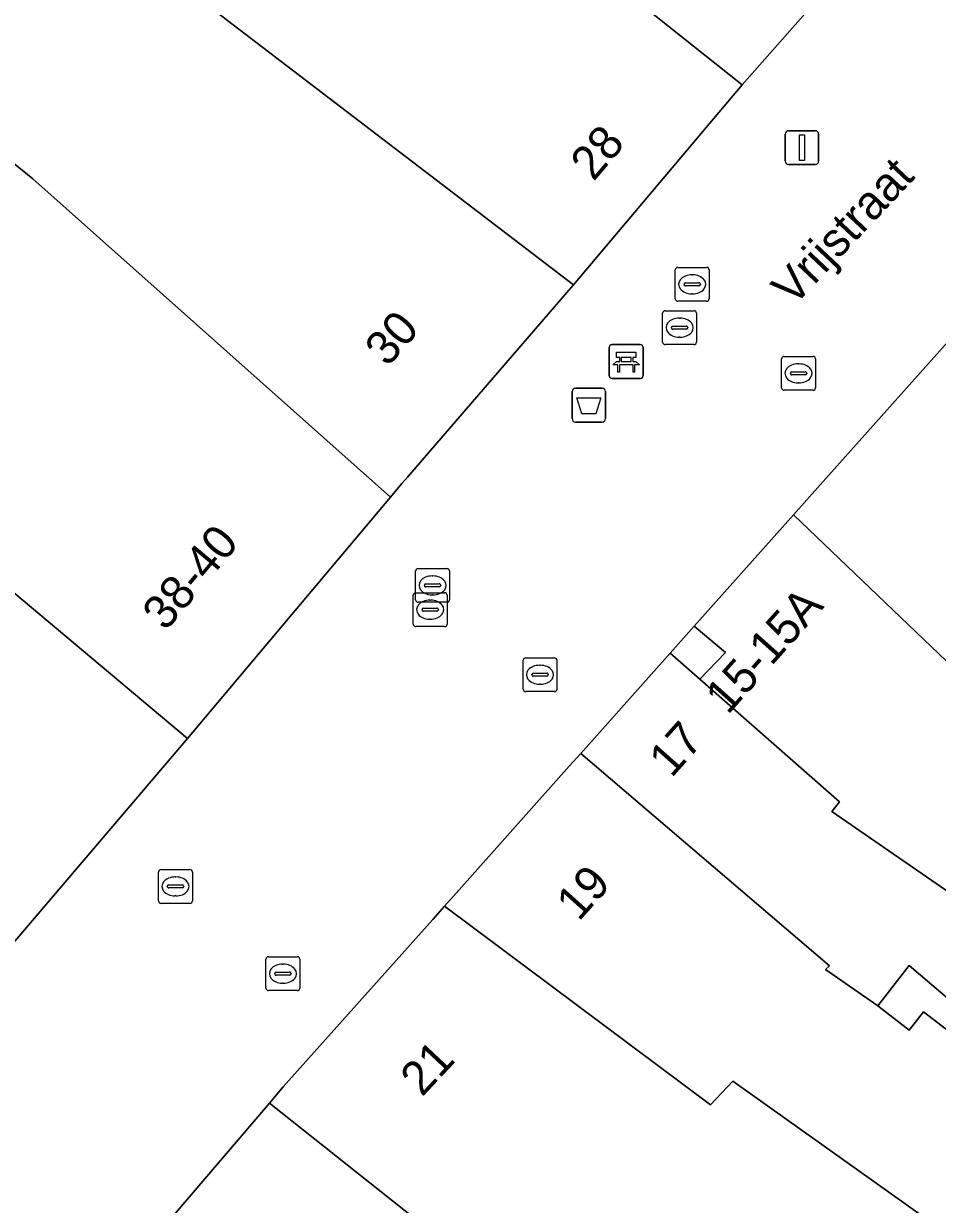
# Model space of a CAD drawing. Extents: x 161087 to 161926, y 382572 to 383873.
# Drawn here: x 161180.41 to 161207.42, y 383266.71 to 383301.6 of the extents above; entities that cross this region are included whole.
import ezdxf

# ---------------------------------------------------------------- set-up
doc = ezdxf.new("R2010")
doc.units = 0
for name, color, linetype in [('IMGEO_Afvalbak', 7, 'Continuous'), ('IMGEO_Bank', 7, 'Continuous'), ('IMGEO_Erf', 7, 'Continuous'), ('IMGEO_Kolk', 7, 'Continuous'), ('IMGEO_Lichtmast', 7, 'Continuous'), ('IMGEO_Openbare_ruimte_label', 7, 'Continuous'), ('IMGEO_Pand', 7, 'Continuous'), ('IMGEO_Pand_nummerreeks', 7, 'Continuous'), ('IMGEO_Pand_overbouw', 7, 'Continuous'), ('IMGEO_Rioolput', 7, 'Continuous'), ('IMGEO_Voetgangersgebied_open', 7, 'Continuous')]:
    doc.layers.add(name, color=color, linetype=linetype)

msp = doc.modelspace()

# ---------------------------------------------------------------- linework, layer by layer
at = {"layer": 'IMGEO_Afvalbak'}
for p, q in [((161196.62, 383289.925), (161196.62, 383290.725)), ((161196.62, 383290.725), (161196.62, 383289.925)), ((161196.72, 383290.825), (161197.51, 383290.825)), ((161197.51, 383290.825), (161196.72, 383290.825)), ((161197.61, 383290.725), (161197.61, 383289.925)), ((161197.61, 383289.925), (161197.61, 383290.725)), ((161197.51, 383289.825), (161196.72, 383289.825)), ((161196.72, 383289.825), (161197.51, 383289.825))]:
    msp.add_line(p, q, dxfattribs=at)
msp.add_lwpolyline([(161196.763, 383290.539), (161197.467, 383290.539), (161197.318, 383290.069), (161196.912, 383290.069), (161196.763, 383290.539)], dxfattribs=at)
for centre, start, end in [((161196.72, 383290.725), 90, 180), ((161196.72, 383290.725), 90, 180), ((161197.51, 383290.725), 0, 90), ((161197.51, 383290.725), 360, 90), ((161196.72, 383289.925), 180, 270), ((161196.72, 383289.925), 180, 270), ((161197.51, 383289.925), 270, 0), ((161197.51, 383289.925), 270, 0)]:
    msp.add_arc(centre, 0.1, start, end, dxfattribs=at)
at = {"layer": 'IMGEO_Bank'}
for p, q in [((161197.72, 383291.188), (161197.72, 383292.029)), ((161197.72, 383292.029), (161197.72, 383291.188)), ((161197.795, 383292.113), (161198.636, 383292.113)), ((161198.636, 383292.113), (161197.795, 383292.113)), ((161198.72, 383292.038), (161198.72, 383291.197)), ((161198.72, 383291.197), (161198.72, 383292.038)), ((161198.029, 383291.619), (161198.029, 383291.725)), ((161198.073, 383291.725), (161198.073, 383291.619)), ((161198.361, 383291.731), (161198.079, 383291.731)), ((161198.367, 383291.619), (161198.367, 383291.725)), ((161198.411, 383291.725), (161198.411, 383291.619)), ((161198.417, 383291.511), (161198.024, 383291.511)), ((161198.079, 383291.613), (161198.361, 383291.613)), ((161198.645, 383291.113), (161197.804, 383291.113)), ((161197.804, 383291.113), (161198.645, 383291.113))]:
    msp.add_line(p, q, dxfattribs=at)
for points in [[(161198.023, 383291.731), (161197.937, 383291.731), (161197.937, 383291.892), (161198.5, 383291.892), (161198.5, 383291.731), (161198.417, 383291.731)], [(161197.967, 383291.511), (161197.825, 383291.511), (161197.937, 383291.613), (161198.023, 383291.613)], [(161198.017, 383291.504), (161198.017, 383291.297), (161197.974, 383291.297), (161197.974, 383291.504)], [(161198.417, 383291.613), (161198.5, 383291.613), (161198.612, 383291.511), (161198.473, 383291.511)], [(161198.467, 383291.504), (161198.467, 383291.297), (161198.423, 383291.297), (161198.423, 383291.504)]]:
    msp.add_lwpolyline(points, dxfattribs=at)
for centre, radius, start, end in [((161197.798, 383292.035), 0.0779, 92.4484, 184.2845), ((161197.798, 383292.035), 0.0779, 92.4484, 184.2845), ((161198.642, 383292.035), 0.0779, 2.4484, 94.2845), ((161198.642, 383292.035), 0.0779, 2.4484, 94.2845), ((161198.022, 383291.724), 0.00671, 2.8957, 87.1043), ((161198.079, 383291.724), 0.00671, 92.8957, 177.1043), ((161198.361, 383291.724), 0.00671, 2.8957, 87.1043), ((161198.418, 383291.724), 0.00671, 92.8957, 177.1043), ((161197.967, 383291.504), 0.00671, 2.8957, 87.1043), ((161198.024, 383291.504), 0.00671, 92.8957, 177.1043), ((161198.022, 383291.62), 0.00671, 272.8957, 357.1043), ((161198.079, 383291.62), 0.00671, 182.8957, 267.1043), ((161198.361, 383291.62), 0.00671, 272.8957, 357.1043), ((161198.418, 383291.62), 0.00671, 182.8957, 267.1043), ((161198.416, 383291.504), 0.00671, 2.8957, 87.1043), ((161198.473, 383291.504), 0.00671, 92.8957, 177.1043), ((161197.798, 383291.191), 0.0779, 182.4484, 274.2845), ((161197.798, 383291.191), 0.0779, 182.4484, 274.2845), ((161198.642, 383291.191), 0.0779, 272.4484, 4.2845), ((161198.642, 383291.191), 0.0779, 272.4484, 4.2845)]:
    msp.add_arc(centre, radius, start, end, dxfattribs=at)
at = {"layer": 'IMGEO_Erf'}
for points in [[(161208.307, 383292.846), (161203.879, 383287.883), (161203.163, 383287.081), (161211.304, 383279.3)], [(161212.075, 383269.087), (161206.58, 383273.763), (161205.662, 383272.572), (161206.589, 383271.857), (161207.009, 383272.401), (161209.012, 383270.858)]]:
    msp.add_lwpolyline(points, dxfattribs=at)
at = {"layer": 'IMGEO_Kolk'}
for p, q in [((161199.67, 383293.468), (161199.67, 383294.32)), ((161199.745, 383294.394), (161200.597, 383294.394)), ((161200.158, 383294.174), (161200.183, 383294.174)), ((161200.671, 383294.32), (161200.671, 383293.468)), ((161199.929, 383293.888), (161199.929, 383293.9)), ((161200.367, 383293.851), (161199.969, 383293.851)), ((161199.972, 383293.937), (161200.37, 383293.937)), ((161200.413, 383293.9), (161200.413, 383293.888)), ((161200.597, 383293.394), (161199.745, 383293.394)), ((161200.181, 383293.614), (161200.156, 383293.614)), ((161202.813, 383290.837), (161202.813, 383291.689)), ((161202.888, 383291.763), (161203.74, 383291.763)), ((161203.814, 383291.689), (161203.814, 383290.837)), ((161203.115, 383291.306), (161203.513, 383291.306)), ((161203.301, 383291.543), (161203.326, 383291.543)), ((161203.072, 383291.257), (161203.072, 383291.269)), ((161203.51, 383291.22), (161203.112, 383291.22)), ((161203.324, 383290.983), (161203.299, 383290.983)), ((161203.556, 383291.269), (161203.556, 383291.257)), ((161203.74, 383290.763), (161202.888, 383290.763)), ((161191.995, 383284.572), (161191.995, 383285.424)), ((161192.07, 383285.498), (161192.922, 383285.498)), ((161192.996, 383285.424), (161192.996, 383284.572)), ((161192.297, 383285.041), (161192.695, 383285.041)), ((161192.483, 383285.278), (161192.508, 383285.278)), ((161192.254, 383284.992), (161192.254, 383285.004)), ((161192.692, 383284.955), (161192.294, 383284.955)), ((161192.506, 383284.718), (161192.481, 383284.718)), ((161192.738, 383285.004), (161192.738, 383284.992)), ((161192.922, 383284.498), (161192.07, 383284.498)), ((161195.173, 383281.932), (161195.173, 383282.784)), ((161195.248, 383282.858), (161196.1, 383282.858)), ((161195.661, 383282.638), (161195.686, 383282.638)), ((161196.174, 383282.784), (161196.174, 383281.932)), ((161195.432, 383282.352), (161195.432, 383282.364)), ((161195.87, 383282.315), (161195.472, 383282.315)), ((161195.475, 383282.401), (161195.873, 383282.401)), ((161195.916, 383282.364), (161195.916, 383282.352)), ((161195.684, 383282.078), (161195.659, 383282.078)), ((161196.1, 383281.858), (161195.248, 383281.858)), ((161184.396, 383275.676), (161184.396, 383276.528)), ((161184.471, 383276.602), (161185.323, 383276.602)), ((161184.884, 383276.382), (161184.909, 383276.382)), ((161185.397, 383276.528), (161185.397, 383275.676)), ((161184.655, 383276.096), (161184.655, 383276.108)), ((161185.093, 383276.059), (161184.695, 383276.059)), ((161184.698, 383276.145), (161185.096, 383276.145)), ((161185.139, 383276.108), (161185.139, 383276.096)), ((161185.323, 383275.602), (161184.471, 383275.602)), ((161184.907, 383275.822), (161184.882, 383275.822)), ((161187.571, 383273.098), (161187.571, 383273.95)), ((161187.646, 383274.024), (161188.498, 383274.024)), ((161188.572, 383273.95), (161188.572, 383273.098)), ((161187.83, 383273.518), (161187.83, 383273.53)), ((161187.873, 383273.567), (161188.271, 383273.567)), ((161188.059, 383273.804), (161188.084, 383273.804)), ((161188.314, 383273.53), (161188.314, 383273.518)), ((161188.268, 383273.481), (161187.87, 383273.481)), ((161188.082, 383273.244), (161188.057, 383273.244)), ((161188.498, 383273.024), (161187.646, 383273.024))]:
    msp.add_line(p, q, dxfattribs=at)
for points in [[(161199.67, 383293.468), (161199.67, 383294.32)], [(161199.745, 383294.394), (161200.597, 383294.394)], [(161200.671, 383294.32), (161200.671, 383293.468)], [(161200.597, 383293.394), (161199.745, 383293.394)], [(161202.813, 383290.837), (161202.813, 383291.689)], [(161202.888, 383291.763), (161203.74, 383291.763)], [(161203.814, 383291.689), (161203.814, 383290.837)], [(161203.74, 383290.763), (161202.888, 383290.763)], [(161191.995, 383284.572), (161191.995, 383285.424)], [(161192.07, 383285.498), (161192.922, 383285.498)], [(161192.996, 383285.424), (161192.996, 383284.572)], [(161192.922, 383284.498), (161192.07, 383284.498)], [(161195.173, 383281.932), (161195.173, 383282.784)], [(161195.248, 383282.858), (161196.1, 383282.858)], [(161196.174, 383282.784), (161196.174, 383281.932)], [(161196.1, 383281.858), (161195.248, 383281.858)], [(161184.396, 383275.676), (161184.396, 383276.528)], [(161184.471, 383276.602), (161185.323, 383276.602)], [(161185.397, 383276.528), (161185.397, 383275.676)], [(161185.323, 383275.602), (161184.471, 383275.602)], [(161187.571, 383273.098), (161187.571, 383273.95)], [(161187.646, 383274.024), (161188.498, 383274.024)], [(161188.572, 383273.95), (161188.572, 383273.098)], [(161188.498, 383273.024), (161187.646, 383273.024)]]:
    msp.add_lwpolyline(points, dxfattribs=at)
for centre, radius, start, end in [((161199.747, 383294.318), 0.0765, 91.552, 178.448), ((161199.747, 383294.318), 0.0765, 91.552, 178.448), ((161200.595, 383294.318), 0.0765, 1.552, 88.448), ((161200.595, 383294.318), 0.0765, 1.552, 88.448), ((161199.969, 383293.897), 0.0403, 85.8775, 175.7526), ((161199.966, 383293.887), 0.0366, 178.938, 274.7102), ((161200.37, 383293.894), 0.043, 264.8664, 352.4533), ((161200.374, 383293.899), 0.0386, 1.7309, 96.639), ((161199.747, 383293.47), 0.0765, 181.552, 268.448), ((161199.747, 383293.47), 0.0765, 181.552, 268.448), ((161200.595, 383293.47), 0.0765, 271.552, 358.448), ((161200.595, 383293.47), 0.0765, 271.552, 358.448), ((161202.89, 383291.687), 0.0765, 91.552, 178.448), ((161202.89, 383291.687), 0.0765, 91.552, 178.448), ((161203.738, 383291.687), 0.0765, 1.552, 88.448), ((161203.738, 383291.687), 0.0765, 1.552, 88.448), ((161203.112, 383291.266), 0.0403, 85.8775, 175.7526), ((161203.517, 383291.268), 0.0386, 1.7309, 96.639), ((161203.109, 383291.256), 0.0366, 178.938, 274.7102), ((161203.513, 383291.263), 0.043, 264.8664, 352.4533), ((161202.89, 383290.839), 0.0765, 181.552, 268.448), ((161202.89, 383290.839), 0.0765, 181.552, 268.448), ((161203.738, 383290.839), 0.0765, 271.552, 358.448), ((161203.738, 383290.839), 0.0765, 271.552, 358.448), ((161192.072, 383285.422), 0.0765, 91.552, 178.448), ((161192.072, 383285.422), 0.0765, 91.552, 178.448), ((161192.92, 383285.422), 0.0765, 1.552, 88.448), ((161192.92, 383285.422), 0.0765, 1.552, 88.448), ((161192.294, 383285.001), 0.0403, 85.8775, 175.7526), ((161192.699, 383285.003), 0.0386, 1.7309, 96.639), ((161192.291, 383284.991), 0.0366, 178.938, 274.7102), ((161192.695, 383284.998), 0.043, 264.8664, 352.4533), ((161192.072, 383284.574), 0.0765, 181.552, 268.448), ((161192.072, 383284.574), 0.0765, 181.552, 268.448), ((161192.92, 383284.574), 0.0765, 271.552, 358.448), ((161192.92, 383284.574), 0.0765, 271.552, 358.448), ((161195.25, 383282.782), 0.0765, 91.552, 178.448), ((161195.25, 383282.782), 0.0765, 91.552, 178.448), ((161196.098, 383282.782), 0.0765, 1.552, 88.448), ((161196.098, 383282.782), 0.0765, 1.552, 88.448), ((161195.472, 383282.361), 0.0403, 85.8775, 175.7526), ((161195.469, 383282.351), 0.0366, 178.938, 274.7102), ((161195.873, 383282.358), 0.043, 264.8664, 352.4533), ((161195.877, 383282.363), 0.0386, 1.7309, 96.639), ((161195.25, 383281.934), 0.0765, 181.552, 268.448), ((161195.25, 383281.934), 0.0765, 181.552, 268.448), ((161196.098, 383281.934), 0.0765, 271.552, 358.448), ((161196.098, 383281.934), 0.0765, 271.552, 358.448), ((161184.473, 383276.526), 0.0765, 91.552, 178.448), ((161184.473, 383276.526), 0.0765, 91.552, 178.448), ((161185.321, 383276.526), 0.0765, 1.552, 88.448), ((161185.321, 383276.526), 0.0765, 1.552, 88.448), ((161184.695, 383276.105), 0.0403, 85.8775, 175.7526), ((161184.692, 383276.095), 0.0366, 178.938, 274.7102), ((161185.096, 383276.102), 0.043, 264.8664, 352.4533), ((161185.1, 383276.107), 0.0386, 1.7309, 96.639), ((161184.473, 383275.678), 0.0765, 181.552, 268.448), ((161184.473, 383275.678), 0.0765, 181.552, 268.448), ((161185.321, 383275.678), 0.0765, 271.552, 358.448), ((161185.321, 383275.678), 0.0765, 271.552, 358.448), ((161187.648, 383273.948), 0.0765, 91.552, 178.448), ((161187.648, 383273.948), 0.0765, 91.552, 178.448), ((161188.496, 383273.948), 0.0765, 1.552, 88.448), ((161188.496, 383273.948), 0.0765, 1.552, 88.448), ((161187.87, 383273.527), 0.0403, 85.8775, 175.7526), ((161187.867, 383273.517), 0.0366, 178.938, 274.7102), ((161188.271, 383273.524), 0.043, 264.8664, 352.4533), ((161188.275, 383273.529), 0.0386, 1.7309, 96.639), ((161187.648, 383273.1), 0.0765, 181.552, 268.448), ((161187.648, 383273.1), 0.0765, 181.552, 268.448), ((161188.496, 383273.1), 0.0765, 271.552, 358.448), ((161188.496, 383273.1), 0.0765, 271.552, 358.448)]:
    msp.add_arc(centre, radius, start, end, dxfattribs=at)
for centre, major_axis, ratio, start_param, end_param in [((161200.157, 383293.894), (-0.387, 0.002), 0.722429, 4.712389, 7.853982), ((161200.182, 383293.894), (-0.39, 0.002), 0.717154, 1.570796, 4.712389), ((161203.3, 383291.263), (-0.387, 0.002), 0.722429, 4.712389, 7.853982), ((161203.325, 383291.263), (-0.39, 0.002), 0.717154, 1.570796, 4.712389), ((161192.482, 383284.998), (-0.387, 0.002), 0.722429, 4.712389, 7.853982), ((161192.507, 383284.998), (-0.39, 0.002), 0.717154, 1.570796, 4.712389), ((161195.66, 383282.358), (-0.387, 0.002), 0.722429, 4.712389, 7.853982), ((161195.685, 383282.358), (-0.39, 0.002), 0.717154, 1.570796, 4.712389), ((161184.883, 383276.102), (-0.387, 0.002), 0.722429, 4.712389, 7.853982), ((161184.908, 383276.102), (-0.39, 0.002), 0.717154, 1.570796, 4.712389), ((161188.058, 383273.524), (-0.387, 0.002), 0.722429, 4.712389, 7.853982), ((161188.083, 383273.524), (-0.39, 0.002), 0.717154, 1.570796, 4.712389)]:
    msp.add_ellipse(centre, major_axis=major_axis, ratio=ratio, start_param=start_param, end_param=end_param, dxfattribs=at)
at = {"layer": 'IMGEO_Lichtmast'}
for p, q in [((161202.918, 383297.533), (161202.918, 383298.333)), ((161202.918, 383298.333), (161202.918, 383297.533)), ((161203.018, 383298.433), (161203.808, 383298.433)), ((161203.808, 383298.433), (161203.018, 383298.433)), ((161203.908, 383298.333), (161203.908, 383297.533)), ((161203.908, 383297.533), (161203.908, 383298.333)), ((161203.808, 383297.433), (161203.018, 383297.433)), ((161203.018, 383297.433), (161203.808, 383297.433))]:
    msp.add_line(p, q, dxfattribs=at)
msp.add_lwpolyline([(161203.338, 383298.308), (161203.488, 383298.308), (161203.488, 383297.558), (161203.338, 383297.558), (161203.338, 383298.308)], dxfattribs=at)
for centre, start, end in [((161203.018, 383298.333), 90, 180), ((161203.018, 383298.333), 90, 180), ((161203.808, 383298.333), 0, 90), ((161203.808, 383298.333), 360, 90), ((161203.018, 383297.533), 180, 270), ((161203.018, 383297.533), 180, 270), ((161203.808, 383297.533), 270, 0), ((161203.808, 383297.533), 270, 0)]:
    msp.add_arc(centre, 0.1, start, end, dxfattribs=at)
at = {"layer": 'IMGEO_Pand'}
for points in [[(161169.587, 383293.626), (161162.431, 383299.673), (161161.277, 383300.648), (161165.502, 383305.649), (161149.625, 383319.064), (161141.622, 383309.593), (161142.279, 383309.038), (161138.369, 383304.424), (161137.707, 383304.978), (161135.611, 383302.499), (161131.326, 383297.432), (161126.068, 383291.213), (161140.496, 383278.979), (161165.893, 383257.765), (161185.253, 383280.475), (161173.986, 383289.923), (161172.743, 383288.452), (161168.405, 383292.227)], [(161184.851, 383302.91), (161170.872, 383314.761), (161168.028, 383311.429), (161169.122, 383310.495), (161167.583, 383308.693), (161167.185, 383308.226), (161169.365, 383306.387), (161176.09, 383300.716), (161180.68, 383297.011), (161191.255, 383287.61), (161191.591, 383288.009), (161191.755, 383288.199), (161196.351, 383293.518), (161196.528, 383293.723), (161196.663, 383293.883)], [(161190.093, 383308.977), (161184.851, 383302.91), (161196.663, 383293.883), (161201.65, 383299.789)], [(161180.68, 383297.011), (161176.09, 383300.716), (161169.365, 383306.387), (161164.484, 383300.903), (161168.251, 383297.615), (161170.086, 383299.717), (161171.14, 383298.826), (161169.016, 383296.313), (161172.011, 383293.783), (161171.255, 383292.889), (161172.187, 383292.102), (161171.856, 383291.709), (161173.986, 383289.923), (161185.253, 383280.475), (161191.255, 383287.61)], [(161203.163, 383287.081), (161200.23, 383283.795), (161201.159, 383283.013), (161200.398, 383282.225), (161204.525, 383278.603), (161204.298, 383278.316), (161208.08, 383275.703), (161211.304, 383279.3)], [(161208.08, 383275.703), (161204.298, 383278.316), (161204.525, 383278.603), (161200.398, 383282.225), (161199.518, 383282.997), (161196.875, 383280.035), (161204.234, 383273.761), (161204.11, 383273.648), (161205.662, 383272.572), (161206.58, 383273.763), (161212.075, 383269.087), (161213.582, 383271.041)], [(161219.145, 383257.549), (161221.267, 383260.303), (161208.475, 383270.161), (161209.012, 383270.858), (161207.009, 383272.401), (161206.589, 383271.857), (161205.662, 383272.572), (161204.11, 383273.648), (161204.234, 383273.761), (161196.875, 383280.035), (161196.536, 383279.655), (161193.279, 383276.005), (161192.845, 383275.519), (161200.709, 383269.651), (161201.372, 383270.345), (161208.609, 383265.2), (161217.208, 383258.346)], [(161217.208, 383258.346), (161208.609, 383265.2), (161201.372, 383270.345), (161200.709, 383269.651), (161192.845, 383275.519), (161192.499, 383275.13), (161188.081, 383270.18), (161187.672, 383269.701), (161194.281, 383264.456), (161196.543, 383262.794), (161197.981, 383264.391), (161199.367, 383263.2), (161199.277, 383262.976), (161203.83, 383259.166), (161214.503, 383251.526), (161214.978, 383252.143), (161219.145, 383257.549)], [(161203.83, 383259.166), (161199.277, 383262.976), (161199.367, 383263.2), (161197.981, 383264.391), (161196.543, 383262.794), (161194.281, 383264.456), (161187.672, 383269.701), (161184.373, 383265.838), (161191.311, 383260.931), (161191.399, 383261.082), (161193.971, 383258.846), (161195.371, 383257.706), (161195.214, 383257.473), (161203.004, 383251.449), (161204.998, 383250), (161218.514, 383240.178), (161219.036, 383240.736), (161220.044, 383241.813), (161223.163, 383245.145), (161223.235, 383245.275), (161216.635, 383250), (161214.503, 383251.526)]]:
    msp.add_lwpolyline(points, close=True, dxfattribs=at)
msp.add_lwpolyline([(161190.093, 383308.977), (161201.65, 383299.789), (161205.895, 383304.607)], dxfattribs=at)
at = {"layer": 'IMGEO_Pand_overbouw'}
msp.add_lwpolyline([(161201.159, 383283.013), (161200.23, 383283.795), (161199.518, 383282.997), (161200.398, 383282.225)], close=True, dxfattribs=at)
at = {"layer": 'IMGEO_Rioolput'}
for p, q in [((161199.297, 383292.188), (161199.297, 383293.04)), ((161199.372, 383293.114), (161200.224, 383293.114)), ((161200.298, 383293.04), (161200.298, 383292.188)), ((161199.785, 383292.894), (161199.81, 383292.894)), ((161199.556, 383292.608), (161199.556, 383292.62)), ((161199.994, 383292.571), (161199.596, 383292.571)), ((161199.599, 383292.657), (161199.997, 383292.657)), ((161199.808, 383292.334), (161199.783, 383292.334)), ((161200.04, 383292.62), (161200.04, 383292.608)), ((161200.224, 383292.114), (161199.372, 383292.114)), ((161191.925, 383283.854), (161191.925, 383284.706)), ((161192, 383284.78), (161192.852, 383284.78)), ((161192.926, 383284.706), (161192.926, 383283.854)), ((161192.227, 383284.323), (161192.625, 383284.323)), ((161192.413, 383284.56), (161192.438, 383284.56)), ((161192.184, 383284.274), (161192.184, 383284.286)), ((161192.622, 383284.237), (161192.224, 383284.237)), ((161192.436, 383284), (161192.411, 383284)), ((161192.668, 383284.286), (161192.668, 383284.274)), ((161192.852, 383283.78), (161192, 383283.78))]:
    msp.add_line(p, q, dxfattribs=at)
for points in [[(161199.297, 383292.188), (161199.297, 383293.04)], [(161199.372, 383293.114), (161200.224, 383293.114)], [(161200.298, 383293.04), (161200.298, 383292.188)], [(161200.224, 383292.114), (161199.372, 383292.114)], [(161191.925, 383283.854), (161191.925, 383284.706)], [(161192, 383284.78), (161192.852, 383284.78)], [(161192.926, 383284.706), (161192.926, 383283.854)], [(161192.852, 383283.78), (161192, 383283.78)]]:
    msp.add_lwpolyline(points, dxfattribs=at)
for centre, radius, start, end in [((161199.374, 383293.038), 0.0765, 91.552, 178.448), ((161199.374, 383293.038), 0.0765, 91.552, 178.448), ((161200.222, 383293.038), 0.0765, 1.552, 88.448), ((161200.222, 383293.038), 0.0765, 1.552, 88.448), ((161199.596, 383292.617), 0.0403, 85.8775, 175.7526), ((161199.593, 383292.607), 0.0366, 178.938, 274.7102), ((161199.997, 383292.614), 0.043, 264.8664, 352.4533), ((161200.001, 383292.619), 0.0386, 1.7309, 96.639), ((161199.374, 383292.19), 0.0765, 181.552, 268.448), ((161199.374, 383292.19), 0.0765, 181.552, 268.448), ((161200.222, 383292.19), 0.0765, 271.552, 358.448), ((161200.222, 383292.19), 0.0765, 271.552, 358.448), ((161192.002, 383284.704), 0.0765, 91.552, 178.448), ((161192.002, 383284.704), 0.0765, 91.552, 178.448), ((161192.85, 383284.704), 0.0765, 1.552, 88.448), ((161192.85, 383284.704), 0.0765, 1.552, 88.448), ((161192.224, 383284.283), 0.0403, 85.8775, 175.7526), ((161192.629, 383284.285), 0.0386, 1.7309, 96.639), ((161192.221, 383284.273), 0.0366, 178.938, 274.7102), ((161192.625, 383284.28), 0.043, 264.8664, 352.4533), ((161192.002, 383283.856), 0.0765, 181.552, 268.448), ((161192.002, 383283.856), 0.0765, 181.552, 268.448), ((161192.85, 383283.856), 0.0765, 271.552, 358.448), ((161192.85, 383283.856), 0.0765, 271.552, 358.448)]:
    msp.add_arc(centre, radius, start, end, dxfattribs=at)
for centre, major_axis, ratio, start_param, end_param in [((161199.784, 383292.614), (-0.387, 0.002), 0.722429, 4.712389, 7.853982), ((161199.809, 383292.614), (-0.39, 0.002), 0.717154, 1.570796, 4.712389), ((161192.412, 383284.28), (-0.387, 0.002), 0.722429, 4.712389, 7.853982), ((161192.437, 383284.28), (-0.39, 0.002), 0.717154, 1.570796, 4.712389)]:
    msp.add_ellipse(centre, major_axis=major_axis, ratio=ratio, start_param=start_param, end_param=end_param, dxfattribs=at)
at = {"layer": 'IMGEO_Voetgangersgebied_open'}
for points in [[(161205.895, 383304.607), (161201.65, 383299.789), (161196.663, 383293.883), (161196.528, 383293.723), (161196.351, 383293.518), (161191.755, 383288.199), (161191.591, 383288.009), (161191.255, 383287.61), (161185.253, 383280.475), (161165.893, 383257.765)], [(161184.373, 383265.838), (161187.672, 383269.701), (161188.081, 383270.18), (161192.499, 383275.13), (161192.845, 383275.519), (161193.279, 383276.005), (161196.536, 383279.655), (161196.875, 383280.035), (161199.518, 383282.997), (161200.398, 383282.225), (161201.159, 383283.013), (161200.23, 383283.795), (161203.163, 383287.081), (161203.879, 383287.883), (161208.307, 383292.846)]]:
    msp.add_lwpolyline(points, dxfattribs=at)

# ---------------------------------------------------------------- texts
at = {"layer": 'IMGEO_Openbare_ruimte_label'}
msp.add_text('Vrijstraat', height=1, rotation=46.7014, dxfattribs=at).set_placement((161203.162, 383293.209))
at = {"layer": 'IMGEO_Pand_nummerreeks'}
for s, rotation, p in [('28', 49.6239, (161197.255, 383296.913)), ('30', 48.8962, (161191.168, 383291.428)), ('38-40', 49.9275, (161184.606, 383283.621)), ('15-15A', 48.2509, (161201.222, 383281.152)), ('17', 48.2574, (161199.557, 383279.285)), ('19', 48.2551, (161196.817, 383275.045)), ('21', 46.8336, (161192.185, 383269.864))]:
    msp.add_text(s, height=1, rotation=rotation, dxfattribs=at).set_placement(p)

doc.saveas('drawing.dxf')
